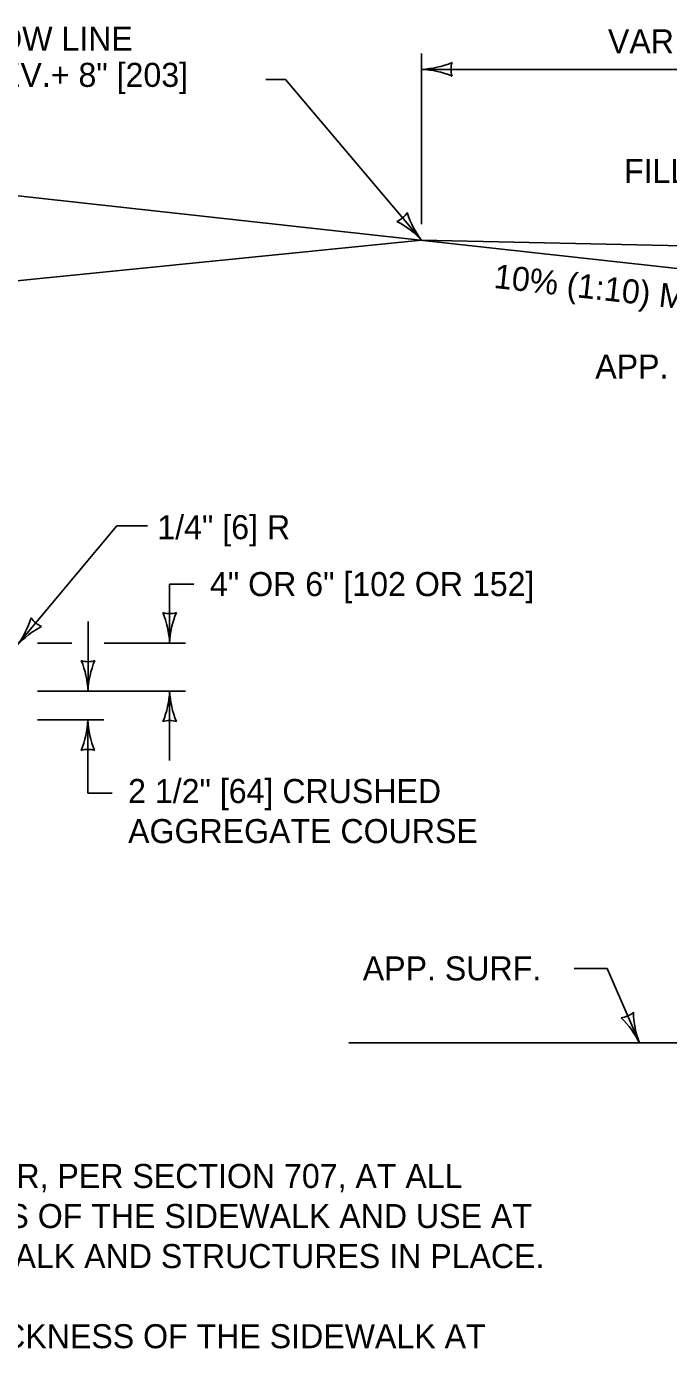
# Model space of a CAD drawing. Extents: x 49987.9 to 50021, y 49987.6 to 50011.4.
# Drawn here: x 50002.674 to 50004.279, y 50003.311 to 50006.611 of the extents above; entities that cross this region are included whole.
import ezdxf

# ---------------------------------------------------------------- set-up
doc = ezdxf.new("R2010")
doc.units = 0
for name, color, linetype in [('Level 1', 7, 'Continuous'), ('Level 2', 7, 'Continuous'), ('Level 3', 7, 'Continuous')]:
    doc.layers.add(name, color=color, linetype=linetype)

msp = doc.modelspace()

# ---------------------------------------------------------------- linework, layer by layer
at = {"layer": 'Level 1'}
for p, q in [((50005.0099, 50005.9293), (50002.004, 50006.2599)), ((50003.6615, 50006.0776), (50001.91, 50005.9023)), ((50003.6615, 50006.0776), (50005.0099, 50006.0493)), ((50003.4796, 50004.0736), (50004.3555, 50004.0737))]:
    msp.add_line(p, q, dxfattribs=at)
at = {"layer": 'Level 3'}
for p, q in [((50003.6615, 50006.1176), (50003.6615, 50006.5442)), ((50003.6615, 50006.5042), (50005.0099, 50006.5042)), ((50003.3211, 50006.4786), (50003.2719, 50006.4786)), ((50003.6615, 50006.0776), (50003.3211, 50006.4786)), ((50002.8997, 50005.3646), (50002.6503, 50005.0657)), ((50002.9769, 50005.3646), (50002.8997, 50005.3646)), ((50003.0319, 50005.072), (50003.0319, 50005.2192)), ((50003.0319, 50005.2192), (50003.0927, 50005.2192)), ((50002.8279, 50004.952), (50002.8279, 50005.1254)), ((50002.7019, 50005.072), (50002.7879, 50005.072)), ((50002.8679, 50005.072), (50003.0719, 50005.072)), ((50002.7019, 50004.952), (50003.0719, 50004.952)), ((50003.0319, 50004.952), (50003.0319, 50004.7785)), ((50002.7019, 50004.88), (50002.8675, 50004.88)), ((50002.8275, 50004.6975), (50002.8275, 50004.88)), ((50002.8275, 50004.6975), (50002.8881, 50004.6975)), ((50004.1249, 50004.2597), (50004.0426, 50004.2597)), ((50004.2058, 50004.0737), (50004.1249, 50004.2597))]:
    msp.add_line(p, q, dxfattribs=at)
for centre, radius, start, end in [((50003.65, 50006.7369), 0.233, 272.8273, 292.0772), ((50003.6524, 50006.2821), 0.2223, 67.456, 87.6395), ((50003.7897, 50006.5042), 0.0548, 162.1388, 197.8612), ((50003.5786, 50006.1753), 0.0548, 292.464, 328.1863), ((50003.8464, 50006.2194), 0.233, 198.248, 217.4978), ((50003.4981, 50005.9269), 0.2223, 42.6856, 62.8691), ((50002.4642, 50005.206), 0.233, 322.9836, 342.2335), ((50002.7324, 50005.1641), 0.0548, 212.2951, 248.0175), ((50003.0319, 50005.2002), 0.0548, 252.1388, 287.8612), ((50002.7992, 50005.0605), 0.233, 2.8273, 22.0772), ((50003.254, 50005.0628), 0.2223, 157.456, 177.6395), ((50002.815, 50004.9164), 0.2223, 117.6123, 137.7958), ((50002.8279, 50005.0802), 0.0548, 252.1388, 287.8612), ((50002.5952, 50004.9405), 0.233, 2.8273, 22.0772), ((50003.05, 50004.9428), 0.2223, 157.456, 177.6395), ((50002.8098, 50004.9611), 0.2223, 337.456, 357.6395), ((50003.2646, 50004.9635), 0.233, 182.8273, 202.0772), ((50002.6054, 50004.8891), 0.2223, 337.456, 357.6395), ((50003.0602, 50004.8915), 0.233, 182.8273, 202.0772), ((50003.0319, 50004.8238), 0.0548, 72.1388, 107.8612), ((50002.8275, 50004.7518), 0.0548, 72.1388, 107.8612), ((50004.1547, 50004.1912), 0.0548, 275.6498, 311.3722), ((50004.4238, 50004.1559), 0.233, 181.4338, 200.6837), ((50004.0058, 50003.9766), 0.2223, 25.8715, 46.055)]:
    msp.add_arc(centre, radius, start, end, dxfattribs=at)

# ---------------------------------------------------------------- texts
at = {"layer": 'Level 2'}
for s, p in [('FLOW LINE', (50002.5075, 50006.5505)), ('VARIABLE', (50004.1271, 50006.5442)), ('ELEV.+ 8" [203]', (50002.5075, 50006.4605)), ('FILLET', (50004.1671, 50006.2207)), ('APP. SURF.', (50004.0955, 50005.7323)), ('1/4" [6] R', (50003.0011, 50005.3312)), ('4" OR 6" [102 OR 152]', (50003.1327, 50005.1892)), ('2 1/2" [64] CRUSHED', (50002.9281, 50004.6725)), ('AGGREGATE COURSE', (50002.9281, 50004.5725)), ('APP. SURF.', (50003.5145, 50004.2297)), ('INSTALL PREFORMED EXPANSION JOINT FILLER, PER SECTION 707, AT ALL', (50000.8077, 50003.7115)), ('EXPANSION JOINTS, FOR THE FULL THICKNESS OF THE SIDEWALK AND USE AT', (50000.8077, 50003.6115)), ('ALL JOINTS BETWEEN NEW CONCRETE SIDEWALK AND STRUCTURES IN PLACE.', (50000.8077, 50003.5115)), ('INSTALL A BOND BREAKER FOR THE FULL THICKNESS OF THE SIDEWALK AT', (50000.8077, 50003.3115))]:
    msp.add_text(s, height=0.06, dxfattribs=at).set_placement(p)
msp.add_text('10% (1:10) MAX.', height=0.06, rotation=353.5455, dxfattribs=at).set_placement((50003.84, 50005.9588))

doc.saveas('drawing.dxf')
